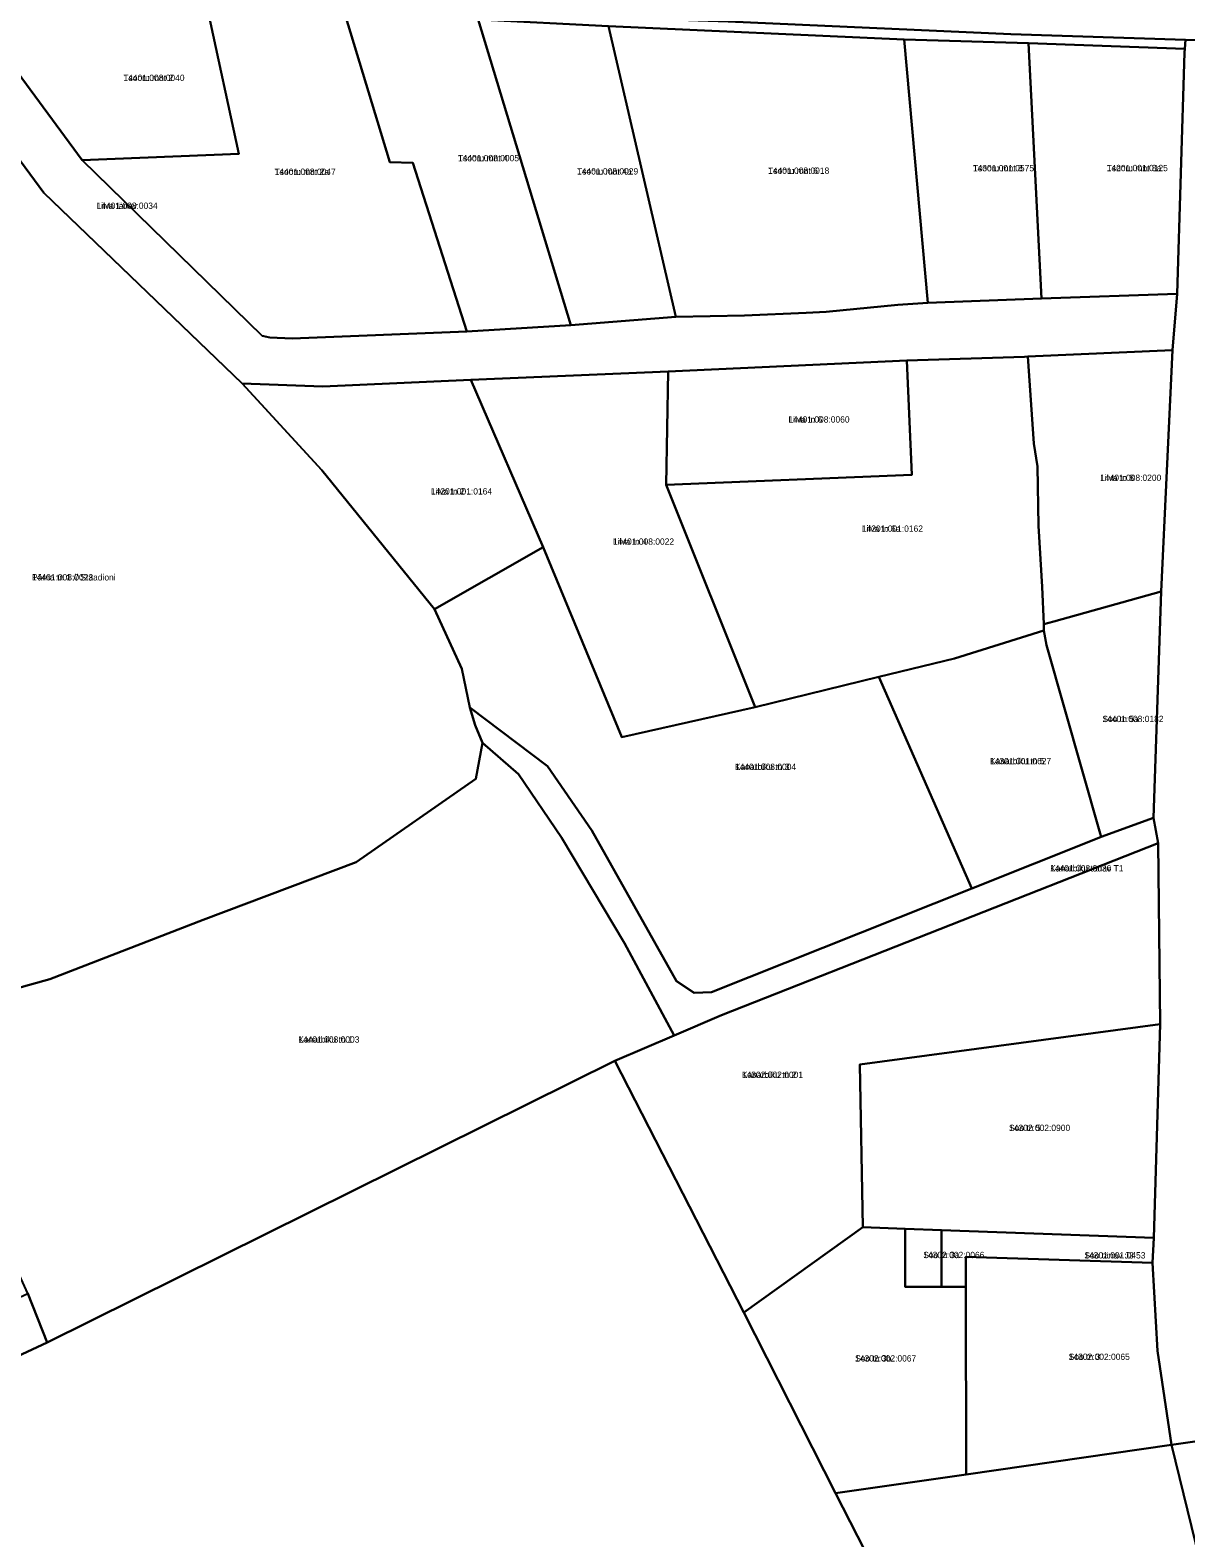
# Model space of a CAD drawing. Extents: x 640657 to 665127, y 6395726 to 6426831.
# Drawn here: x 650844.3 to 651118.5, y 6412092.9 to 6412450.8 of the extents above; entities that cross this region are included whole.
import ezdxf

# ---------------------------------------------------------------- set-up
doc = ezdxf.new("R2010")
doc.units = 0
for name, color, linetype in [('L_AADRESS', 7, 'Continuous'), ('PIIR', 7, 'Continuous'), ('TUNNUS', 7, 'Continuous')]:
    doc.layers.add(name, color=color, linetype=linetype)

msp = doc.modelspace()

# ---------------------------------------------------------------- linework, layer by layer
at = {"layer": 'PIIR'}
for points in [[(650833.55, 6412451.31), (650847.46, 6412457.49), (650886.48, 6412455.5), (650893.8, 6412421.45), (650856.7, 6412419.97), (650834.15, 6412450.5)], [(650847.46, 6412457.49), (650921.15, 6412455.52), (650957.96, 6412454.62), (651009.94, 6412452.82), (651076.96, 6412449.83), (651118.4, 6412448.5), (651118.26, 6412446.38), (651081.18, 6412447.69), (651051.7, 6412448.6), (650981.5, 6412451.78), (650950.64, 6412453.3), (650919.01, 6412454.64), (650886.48, 6412455.5)], [(650886.48, 6412455.5), (650919.01, 6412454.64), (650929.62, 6412419.44), (650935.08, 6412419.27), (650947.93, 6412379.24), (650906.5, 6412377.57), (650901.18, 6412377.87), (650899.4, 6412378.27), (650856.7, 6412419.97), (650893.8, 6412421.45)], [(650950.64, 6412453.3), (650972.6, 6412380.8), (650947.93, 6412379.24), (650935.08, 6412419.27), (650929.62, 6412419.44), (650919.01, 6412454.64)], [(650950.64, 6412453.3), (650981.5, 6412451.78), (650997.5, 6412382.74), (650972.6, 6412380.8)], [(651051.7, 6412448.6), (651057.3, 6412386.1), (651050.2, 6412385.6), (651033.2, 6412383.9), (651028.4, 6412383.7), (651013.8, 6412383.09), (650997.5, 6412382.74), (650981.5, 6412451.78)], [(651051.7, 6412448.6), (651081.18, 6412447.69), (651084.24, 6412387.06), (651057.3, 6412386.1)], [(651084.24, 6412387.06), (651081.18, 6412447.69), (651118.26, 6412446.38), (651118.2, 6412445.5), (651116.4, 6412388.2)], [(651016.31, 6412290.13), (650995.21, 6412342.89), (651053.52, 6412345.22), (651052.31, 6412372.39), (651080.2, 6412373.28), (651081.02, 6412373.31), (651082.41, 6412352.7), (651083.28, 6412347.19), (651083.5, 6412333.15), (651084.37, 6412318.69), (651084.77, 6412309.81), (651084.84, 6412308.32), (651063.64, 6412301.61), (651045.68, 6412297.33)], [(651112.6, 6412317.56), (651087.17, 6412310.45), (651084.77, 6412309.81), (651084.37, 6412318.69), (651083.5, 6412333.15), (651083.28, 6412347.19), (651082.41, 6412352.7), (651081.02, 6412373.31), (651115.3, 6412374.83)], [(650948.87, 6412367.79), (650995.68, 6412369.75), (650995.21, 6412342.89), (651016.31, 6412290.13), (650984.72, 6412282.95), (650966.03, 6412328.11)], [(651052.31, 6412372.39), (651053.52, 6412345.22), (650995.21, 6412342.89), (650995.68, 6412369.75)], [(650913.51, 6412346.32), (650894.61, 6412366.94), (650913.78, 6412366.24), (650948.87, 6412367.79), (650966.03, 6412328.11), (650940.28, 6412313.36)], [(650940.28, 6412313.36), (650966.03, 6412328.11), (650984.72, 6412282.95), (651016.31, 6412290.13), (651045.68, 6412297.33), (651067.7, 6412247.08), (651005.97, 6412222.48), (651001.82, 6412222.27), (650997.67, 6412225.02), (650977.59, 6412260.85), (650967.03, 6412276.12), (650948.64, 6412290.03), (650946.75, 6412299.23)], [(651112.6, 6412317.56), (651110.81, 6412263.85), (651098.39, 6412259.32), (651098.14, 6412260.09), (651085.41, 6412304.83), (651084.84, 6412308.32), (651084.77, 6412309.81), (651087.17, 6412310.45)], [(651097.47, 6412258.95), (651067.7, 6412247.08), (651045.68, 6412297.33), (651063.64, 6412301.61), (651084.84, 6412308.32), (651085.41, 6412304.83), (651098.14, 6412260.09), (651098.39, 6412259.32)], [(650948.64, 6412290.03), (650967.03, 6412276.12), (650977.59, 6412260.85), (650997.67, 6412225.02), (651001.82, 6412222.27), (651005.97, 6412222.48), (651067.7, 6412247.08), (651097.47, 6412258.95), (651098.39, 6412259.32), (651110.81, 6412263.85), (651111.93, 6412257.81), (651008.36, 6412217.01), (650997.08, 6412212.14), (650985.32, 6412234.06), (650970.35, 6412259.19), (650960.19, 6412274.16), (650951.64, 6412281.64), (650949.9, 6412285.8)], [(650997.08, 6412212.14), (650983.04, 6412206.16), (650848.37, 6412139.28), (650843.75, 6412150.93), (650834.44, 6412171.36), (650835.66, 6412172.48), (650825.12, 6412196.14), (650828.58, 6412198.31), (650819.46, 6412217.33), (650848.99, 6412225.51), (650885.41, 6412239.63), (650921.7, 6412253.31), (650950.03, 6412273.09), (650951.64, 6412281.64), (650960.19, 6412274.16), (650970.35, 6412259.19), (650985.32, 6412234.06)], [(651111.93, 6412257.81), (651112.42, 6412214.85), (651041.17, 6412205.28), (651041.83, 6412166.63), (651013.66, 6412146.38), (650983.04, 6412206.16), (650997.08, 6412212.14), (651008.36, 6412217.01)], [(651041.17, 6412205.28), (651112.42, 6412214.85), (651110.92, 6412164.11), (651060.5, 6412165.95), (651051.9, 6412166.3), (651041.83, 6412166.63)], [(650983.04, 6412206.16), (651013.66, 6412146.38), (651035.34, 6412103.54), (651075.36, 6412025.23), (651049.71, 6412021.34), (651050.96, 6411983.58), (650908.42, 6411918.41), (650898.06, 6411957.13), (650834.4, 6411933.05), (650780.5, 6412107.64), (650848.37, 6412139.28)], [(651013.66, 6412146.38), (651041.83, 6412166.63), (651051.9, 6412166.3), (651051.9, 6412152.5), (651060.5, 6412152.5), (651066.3, 6412152.5), (651066.4, 6412107.97), (651035.34, 6412103.54)], [(651060.5, 6412165.95), (651060.5, 6412152.5), (651051.9, 6412152.5), (651051.9, 6412166.3)], [(651060.5, 6412165.95), (651110.92, 6412164.11), (651110.6, 6412158.2), (651066.3, 6412159.6), (651066.3, 6412152.5), (651060.5, 6412152.5)], [(651110.6, 6412158.2), (651111.8, 6412137.3), (651115.11, 6412114.98), (651066.4, 6412107.97), (651066.3, 6412152.5), (651066.3, 6412159.6)], [(650780.5, 6412107.64), (650775.61, 6412120.12), (650781.62, 6412122.52), (650843.75, 6412150.93), (650848.37, 6412139.28)], [(651127.44, 6412064.62), (651115.11, 6412114.98), (651127.2, 6412116.75), (651137.28, 6412074.84), (651139.2, 6412066.86)], [(651075.36, 6412025.23), (651035.34, 6412103.54), (651066.4, 6412107.97), (651115.11, 6412114.98), (651127.44, 6412064.62), (651139.2, 6412066.86), (651139.54, 6412065.49), (651158.57, 6412059.79), (651226.01, 6412069.15), (651231.91, 6412078.23), (651238.71, 6412077.37), (651249.57, 6412061.32), (651252.58, 6412040.77), (651253.25, 6412015.88), (651185.77, 6412000.07), (651150.63, 6411998.61), (651078.55, 6411995.77), (651050.96, 6411983.58), (651049.71, 6412021.34)]]:
    msp.add_lwpolyline(points, close=True, dxfattribs=at)
for points in [[(651125.38, 6412448.34), (651118.4, 6412448.5), (651076.96, 6412449.83), (651009.94, 6412452.82)], [(650834.15, 6412450.5), (650856.7, 6412419.97), (650899.4, 6412378.27), (650901.18, 6412377.87), (650906.5, 6412377.57), (650947.93, 6412379.24), (650972.6, 6412380.8), (650997.5, 6412382.74), (651013.8, 6412383.09), (651028.4, 6412383.7), (651033.2, 6412383.9), (651050.2, 6412385.6), (651057.3, 6412386.1), (651084.24, 6412387.06), (651116.4, 6412388.2), (651115.3, 6412374.83), (651081.02, 6412373.31), (651080.2, 6412373.28), (651052.31, 6412372.39), (650995.68, 6412369.75), (650948.87, 6412367.79), (650913.78, 6412366.24), (650894.61, 6412366.94), (650847.6, 6412412.2), (650832.2, 6412432.9)], [(651127.2, 6412116.75), (651115.11, 6412114.98), (651111.8, 6412137.3), (651110.6, 6412158.2), (651110.92, 6412164.11), (651112.42, 6412214.85), (651111.93, 6412257.81), (651110.81, 6412263.85), (651112.6, 6412317.56), (651115.3, 6412374.83), (651116.4, 6412388.2), (651118.2, 6412445.5), (651118.26, 6412446.38), (651118.4, 6412448.5), (651125.38, 6412448.34)], [(650832.2, 6412432.9), (650847.6, 6412412.2), (650894.61, 6412366.94), (650913.51, 6412346.32), (650940.28, 6412313.36), (650946.75, 6412299.23), (650948.64, 6412290.03), (650949.9, 6412285.8), (650951.64, 6412281.64), (650950.03, 6412273.09), (650921.7, 6412253.31), (650885.41, 6412239.63), (650848.99, 6412225.51), (650819.46, 6412217.33)]]:
    msp.add_lwpolyline(points, dxfattribs=at)

# ---------------------------------------------------------------- texts
at = {"layer": 'L_AADRESS'}
for s, p in [('Tsooru mnt 2', (650866.46, 6412438.73)), ('Tsooru mnt 4', (650945.8, 6412419.68)), ('Tsooru mnt 2a', (650902.32, 6412416.44)), ('Tsooru mnt 4a', (650974.07, 6412416.53)), ('Tsooru mnt 6', (651019.4, 6412416.69)), ('Tsooru mnt 8', (651067.97, 6412417.29)), ('Tsooru mnt 8a', (651099.72, 6412417.32)), ('Liiva tänav', (650860.08, 6412408.37)), ('Liiva tn 6', (651024.22, 6412357.64)), ('Liiva tn 8', (651098.16, 6412343.8)), ('Liiva tn 2', (650939.41, 6412340.57)), ('Liiva tn 4', (650982.59, 6412328.65)), ('Liiva tn 6a', (651041.63, 6412331.72)), ('Pärna tn 1 // Staadioni', (650844.77, 6412320.17)), ('Soo tn 5a', (651098.69, 6412286.55)), ('Kanarbiku tn 3', (651011.53, 6412275.19)), ('Kanarbiku tn 5', (651072.04, 6412276.54)), ('Kanarbiku tänav T1', (651086.3, 6412251.09)), ('Kanarbiku tn 1', (650907.94, 6412210.46)), ('Kanarbiku tn 2', (651013.17, 6412202.09)), ('Soo tn 5', (651076.55, 6412189.48)), ('Soo tn 3a', (651056.2, 6412159.31)), ('Soo tänav J3', (651094.41, 6412159.23)), ('Soo tn 3', (651090.7, 6412135.15)), ('Soo tn 3b', (651040.03, 6412134.77))]:
    msp.add_text(s, height=1.5, dxfattribs=at).set_placement(p)
at = {"layer": 'TUNNUS'}
for s, p in [('14401:008:0040', (650866.46, 6412438.73)), ('14401:008:0005', (650945.8, 6412419.68)), ('14401:008:0047', (650902.32, 6412416.44)), ('14401:008:0029', (650974.07, 6412416.53)), ('14401:008:0018', (651019.4, 6412416.69)), ('14301:001:0575', (651067.97, 6412417.29)), ('14201:001:0125', (651099.72, 6412417.32)), ('14401:008:0034', (650860.08, 6412408.37)), ('14401:008:0060', (651024.22, 6412357.64)), ('14401:008:0200', (651098.16, 6412343.8)), ('14201:001:0164', (650939.41, 6412340.57)), ('14401:008:0022', (650982.59, 6412328.65)), ('14201:001:0162', (651041.63, 6412331.72)), ('14401:008:0023', (650844.77, 6412320.17)), ('14401:008:0182', (651098.69, 6412286.55)), ('14401:008:0004', (651011.53, 6412275.19)), ('14301:001:0627', (651072.04, 6412276.54)), ('14401:008:0036', (651086.3, 6412251.09)), ('14401:008:0003', (650907.94, 6412210.46)), ('14302:002:0001', (651013.17, 6412202.09)), ('14302:002:0900', (651076.55, 6412189.48)), ('14302:002:0066', (651056.2, 6412159.31)), ('14301:001:0453', (651094.41, 6412159.23)), ('14302:002:0065', (651090.7, 6412135.15)), ('14302:002:0067', (651040.03, 6412134.77))]:
    msp.add_text(s, height=1.5, dxfattribs=at).set_placement(p)

doc.saveas('drawing.dxf')
